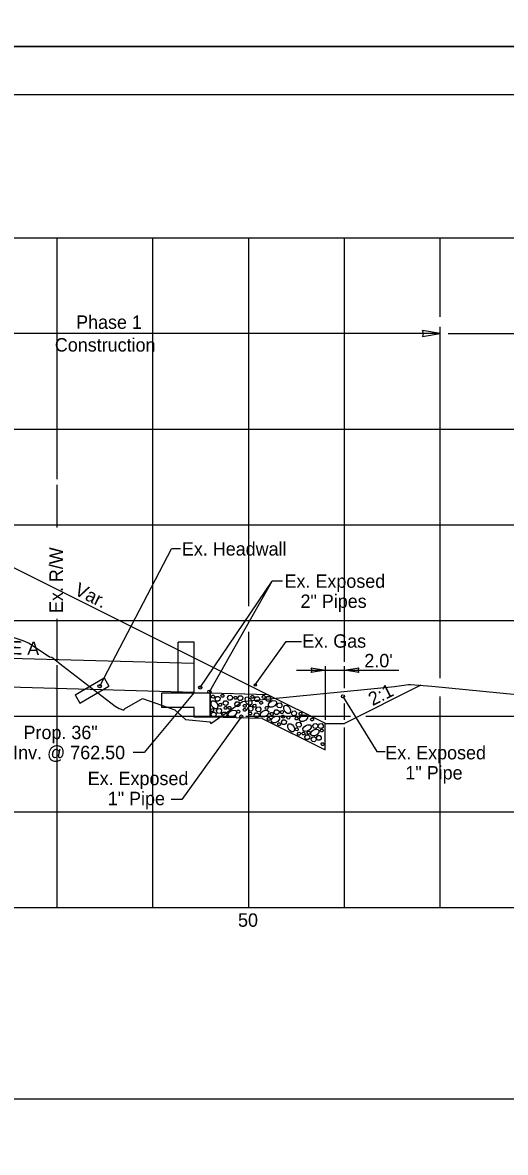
# Model space of a CAD drawing. Extents: x -1395 to 1843, y -1176 to 1887.
# Drawn here: x 387.8 to 488.6, y -671.2 to -435 of the extents above; entities that cross this region are included whole.
import ezdxf

# ---------------------------------------------------------------- set-up
doc = ezdxf.new("R2010")
doc.units = 0
for name, color, linetype in [('Default', 7, 'Continuous'), ('DR_P_Paved_Gutter', 7, 'Continuous'), ('DR_X_Storm_Sewer', 7, 'Continuous'), ('GE_X_Alignment', 7, 'Continuous'), ('HY_X_Water_Edge', 7, 'Continuous'), ('MT_P_Temp_Road', 7, 'Continuous'), ('PV_X_Shoulder', 7, 'Continuous'), ('RW_P_Esmt_TMP', 7, 'Continuous'), ('SH_Border', 7, 'Continuous'), ('SH_Cut_Line', 7, 'Continuous'), ('SH_Data', 7, 'Continuous'), ('SH_Major_Grid_Line', 7, 'Continuous'), ('SH_Named_Boundary', 7, 'Continuous'), ('SV_X_Shot_Marker', 7, 'Continuous'), ('SV_X_Terrain_Boundary', 7, 'Continuous'), ('SV_X_Toe_of_Slope', 7, 'Continuous'), ('SV_X_Top_of_Bank', 7, 'Continuous'), ('XS_P_Pavt_Surface', 7, 'Continuous')]:
    doc.layers.add(name, color=color, linetype=linetype)

msp = doc.modelspace()

# ---------------------------------------------------------------- linework, layer by layer
at = {"layer": 'Default'}
for p, q in [((475, -500), (471.29, -499.38)), ((471.29, -499.38), (471.29, -499.38)), ((471.3, -500.62), (475, -500)), ((471.3, -500.62), (471.3, -500.62))]:
    msp.add_line(p, q, dxfattribs=at)
msp.add_arc((470.36, -500.01), 1.12, 327.1412, 33.822, dxfattribs=at)
at = {"layer": 'DR_P_Paved_Gutter'}
for p, q in [((426.95, -575.17), (426.95, -580.17)), ((439.08, -575.51), (426.95, -575.17)), ((439.08, -575.51), (450.95, -581.44)), ((437.84, -580.47), (426.95, -580.17)), ((437.84, -580.47), (450.95, -587.03)), ((450.95, -587.03), (450.95, -581.44))]:
    msp.add_line(p, q, dxfattribs=at)
for points in [[(427.21, -575.85), (427.38, -575.62), (427.65, -575.6), (427.84, -575.79), (427.81, -576.06), (427.64, -576.2), (427.38, -576.18), (427.25, -576.06), (427.21, -575.85)], [(427.98, -576.27), (428.26, -575.87), (428.7, -575.84), (429.01, -576.16), (428.97, -576.62), (428.69, -576.85), (428.25, -576.81), (428.04, -576.61), (427.98, -576.27)], [(429.21, -575.69), (429.38, -575.45), (429.64, -575.44), (429.83, -575.63), (429.8, -575.9), (429.64, -576.04), (429.37, -576.02), (429.25, -575.9), (429.21, -575.69)], [(430.54, -576.05), (430.82, -575.65), (431.27, -575.62), (431.58, -575.95), (431.53, -576.4), (431.26, -576.63), (430.82, -576.6), (430.61, -576.39), (430.54, -576.05)], [(431.92, -576.09), (432.09, -575.85), (432.36, -575.84), (432.55, -576.03), (432.52, -576.3), (432.35, -576.44), (432.09, -576.42), (431.97, -576.3), (431.92, -576.09)], [(432.74, -576.14), (433.02, -575.74), (433.46, -575.71), (433.78, -576.04), (433.73, -576.49), (433.45, -576.72), (433.01, -576.69), (432.81, -576.48), (432.74, -576.14)], [(435.46, -576.43), (435.66, -576.96), (435.62, -577.44), (435.4, -577.67), (435.01, -577.66), (434.57, -577.31), (434.3, -576.78), (434.29, -576.27), (434.49, -575.99), (434.9, -575.96), (435.26, -576.19), (435.47, -576.45)], [(435.46, -575.89), (435.62, -575.65), (435.89, -575.64), (436.08, -575.83), (436.05, -576.1), (435.89, -576.24), (435.62, -576.22), (435.5, -576.1), (435.46, -575.89)], [(436.22, -576.35), (436.5, -575.95), (436.95, -575.93), (437.26, -576.25), (437.21, -576.7), (436.94, -576.93), (436.49, -576.9), (436.29, -576.7), (436.22, -576.35)], [(437.82, -575.92), (437.99, -575.68), (438.25, -575.67), (438.44, -575.86), (438.41, -576.13), (438.25, -576.27), (437.98, -576.25), (437.86, -576.13), (437.82, -575.92)], [(438.6, -576.27), (438.88, -575.87), (439.33, -575.84), (439.64, -576.17), (439.6, -576.62), (439.32, -576.85), (438.88, -576.82), (438.67, -576.61), (438.61, -576.27)], [(427.06, -578.66), (427.23, -578.42), (427.5, -578.4), (427.68, -578.6), (427.66, -578.87), (427.49, -579), (427.23, -578.99), (427.1, -578.86), (427.06, -578.66)], [(428.34, -577.22), (428.55, -577.74), (428.5, -578.23), (428.29, -578.46), (427.9, -578.45), (427.45, -578.1), (427.18, -577.56), (427.17, -577.06), (427.38, -576.77), (427.78, -576.75), (428.14, -576.98), (428.35, -577.24)], [(428.29, -578.82), (428.57, -578.43), (429.02, -578.4), (429.33, -578.72), (429.28, -579.17), (429.01, -579.4), (428.56, -579.37), (428.36, -579.17), (428.29, -578.82)], [(428.72, -577.54), (428.89, -577.3), (429.16, -577.29), (429.34, -577.48), (429.32, -577.75), (429.15, -577.89), (428.88, -577.87), (428.76, -577.75), (428.72, -577.54)], [(429.67, -577.16), (429.95, -576.76), (430.39, -576.74), (430.71, -577.06), (430.66, -577.51), (430.38, -577.74), (429.94, -577.71), (429.74, -577.51), (429.67, -577.16)], [(429.84, -578.21), (430.01, -577.97), (430.28, -577.95), (430.46, -578.15), (430.44, -578.42), (430.27, -578.55), (430, -578.54), (429.88, -578.41), (429.84, -578.21)], [(430.67, -578.18), (430.84, -577.94), (431.1, -577.93), (431.29, -578.12), (431.26, -578.39), (431.1, -578.53), (430.83, -578.51), (430.71, -578.39), (430.67, -578.18)], [(432.13, -577.41), (432.41, -577.01), (432.86, -576.99), (433.17, -577.31), (433.13, -577.76), (432.85, -577.99), (432.41, -577.96), (432.2, -577.76), (432.13, -577.41)], [(433.85, -578.6), (434.02, -578.36), (434.29, -578.35), (434.48, -578.54), (434.45, -578.81), (434.29, -578.95), (434.02, -578.93), (433.9, -578.81), (433.85, -578.6)], [(433.87, -577.78), (434.03, -577.55), (434.3, -577.53), (434.49, -577.72), (434.46, -577.99), (434.3, -578.13), (434.03, -578.11), (433.91, -577.99), (433.87, -577.78)], [(434.85, -578.32), (435.13, -577.92), (435.58, -577.89), (435.89, -578.22), (435.85, -578.67), (435.57, -578.9), (435.13, -578.87), (434.92, -578.67), (434.85, -578.32)], [(435.89, -577.75), (436.06, -577.51), (436.33, -577.5), (436.52, -577.69), (436.49, -577.96), (436.32, -578.1), (436.06, -578.08), (435.94, -577.96), (435.89, -577.75)], [(436.5, -578.49), (436.78, -578.09), (437.23, -578.06), (437.54, -578.38), (437.49, -578.84), (437.22, -579.07), (436.77, -579.03), (436.57, -578.83), (436.5, -578.49)], [(437.27, -577.14), (437.44, -576.9), (437.71, -576.88), (437.89, -577.08), (437.87, -577.35), (437.7, -577.49), (437.43, -577.47), (437.31, -577.34), (437.27, -577.14)], [(438.43, -578.21), (438.6, -577.97), (438.87, -577.96), (439.05, -578.15), (439.02, -578.42), (438.86, -578.56), (438.59, -578.54), (438.47, -578.42), (438.43, -578.21)], [(439.58, -576.91), (440.11, -576.71), (440.59, -576.75), (440.82, -576.96), (440.81, -577.36), (440.46, -577.8), (439.93, -578.07), (439.42, -578.08), (439.14, -577.87), (439.11, -577.47), (439.34, -577.11), (439.6, -576.9)], [(440.89, -577.64), (441.17, -577.25), (441.62, -577.22), (441.93, -577.54), (441.89, -577.99), (441.61, -578.22), (441.17, -578.19), (440.96, -577.99), (440.89, -577.64)], [(443.5, -578.18), (443.71, -578.71), (443.67, -579.19), (443.45, -579.42), (443.06, -579.41), (442.61, -579.06), (442.34, -578.53), (442.34, -578.02), (442.54, -577.74), (442.94, -577.71), (443.3, -577.94), (443.51, -578.2)], [(427.13, -579.53), (427.41, -579.13), (427.86, -579.11), (428.17, -579.43), (428.12, -579.88), (427.84, -580.11), (427.4, -580.08), (427.2, -579.88), (427.13, -579.53)], [(429.42, -579.55), (429.7, -579.15), (430.15, -579.12), (430.46, -579.45), (430.42, -579.9), (430.14, -580.13), (429.7, -580.1), (429.49, -579.89), (429.42, -579.55)], [(431.21, -578.94), (431.73, -578.73), (432.21, -578.78), (432.44, -578.99), (432.43, -579.38), (432.09, -579.83), (431.55, -580.1), (431.04, -580.11), (430.76, -579.9), (430.73, -579.5), (430.96, -579.14), (431.23, -578.93)], [(432.5, -578.97), (432.67, -578.73), (432.94, -578.72), (433.12, -578.91), (433.1, -579.18), (432.93, -579.32), (432.66, -579.3), (432.54, -579.18), (432.5, -578.97)], [(434.99, -579.38), (435.16, -579.14), (435.43, -579.12), (435.61, -579.31), (435.59, -579.59), (435.42, -579.72), (435.16, -579.7), (435.03, -579.58), (434.99, -579.38)], [(436.11, -579.69), (436.39, -579.29), (436.84, -579.26), (437.15, -579.58), (437.1, -580.04), (436.83, -580.27), (436.39, -580.23), (436.18, -580.03), (436.11, -579.69)], [(437.93, -578.95), (438.46, -578.74), (438.94, -578.78), (439.17, -579), (439.16, -579.39), (438.81, -579.83), (438.28, -580.1), (437.77, -580.11), (437.49, -579.91), (437.46, -579.51), (437.69, -579.15), (437.96, -578.94)], [(438.86, -580.52), (439.03, -580.28), (439.3, -580.27), (439.48, -580.46), (439.46, -580.73), (439.29, -580.87), (439.03, -580.85), (438.9, -580.73), (438.86, -580.52)], [(439.51, -579.47), (439.68, -579.23), (439.95, -579.22), (440.13, -579.41), (440.11, -579.68), (439.94, -579.82), (439.68, -579.8), (439.55, -579.68), (439.51, -579.47)], [(440.18, -580.18), (440.71, -579.97), (441.19, -580.02), (441.42, -580.23), (441.41, -580.62), (441.06, -581.07), (440.52, -581.34), (440.02, -581.34), (439.73, -581.14), (439.71, -580.74), (439.94, -580.38), (440.2, -580.17)], [(440.3, -579.05), (440.58, -578.65), (441.02, -578.63), (441.33, -578.95), (441.29, -579.4), (441.01, -579.63), (440.57, -579.6), (440.36, -579.4), (440.3, -579.05)], [(441.62, -579.07), (441.79, -578.83), (442.06, -578.81), (442.25, -579.01), (442.22, -579.28), (442.06, -579.42), (441.79, -579.4), (441.67, -579.28), (441.63, -579.07)], [(441.83, -581.14), (442.11, -580.74), (442.56, -580.72), (442.87, -581.04), (442.82, -581.49), (442.55, -581.72), (442.11, -581.69), (441.9, -581.49), (441.83, -581.14)], [(441.86, -580.03), (442.02, -579.79), (442.29, -579.78), (442.48, -579.97), (442.45, -580.24), (442.29, -580.38), (442.02, -580.36), (441.9, -580.24), (441.86, -580.03)], [(442.96, -580.23), (443.13, -579.99), (443.4, -579.98), (443.58, -580.17), (443.55, -580.44), (443.39, -580.58), (443.12, -580.56), (443, -580.44), (442.96, -580.23)], [(443.94, -579.32), (444.22, -578.92), (444.66, -578.89), (444.97, -579.21), (444.93, -579.67), (444.65, -579.9), (444.21, -579.86), (444, -579.66), (443.94, -579.32)], [(444.67, -580.39), (444.84, -580.15), (445.1, -580.14), (445.29, -580.33), (445.26, -580.6), (445.1, -580.74), (444.83, -580.72), (444.71, -580.6), (444.67, -580.39)], [(445.5, -579.43), (445.67, -579.19), (445.94, -579.17), (446.12, -579.36), (446.1, -579.64), (445.93, -579.77), (445.67, -579.75), (445.54, -579.63), (445.5, -579.43)], [(446.05, -579.92), (446.58, -579.72), (447.06, -579.76), (447.29, -579.97), (447.28, -580.37), (446.93, -580.81), (446.39, -581.08), (445.89, -581.09), (445.6, -580.88), (445.58, -580.48), (445.81, -580.12), (446.07, -579.91)], [(447.92, -580.62), (448.09, -580.39), (448.36, -580.37), (448.54, -580.56), (448.52, -580.83), (448.35, -580.97), (448.08, -580.95), (447.96, -580.83), (447.92, -580.62)], [(441.01, -581.62), (441.18, -581.38), (441.45, -581.36), (441.64, -581.55), (441.61, -581.83), (441.44, -581.96), (441.18, -581.94), (441.06, -581.82), (441.01, -581.62)], [(444.35, -582.03), (444.56, -582.55), (444.52, -583.03), (444.3, -583.26), (443.91, -583.25), (443.47, -582.91), (443.2, -582.37), (443.19, -581.86), (443.39, -581.58), (443.79, -581.55), (444.15, -581.78), (444.36, -582.05)], [(444.7, -582.67), (444.87, -582.43), (445.14, -582.42), (445.33, -582.61), (445.3, -582.88), (445.13, -583.02), (444.87, -583), (444.74, -582.88), (444.7, -582.67)], [(444.93, -581.68), (445.21, -581.28), (445.65, -581.26), (445.96, -581.58), (445.92, -582.03), (445.64, -582.26), (445.2, -582.23), (444.99, -582.03), (444.93, -581.68)], [(446.11, -583.55), (446.28, -583.31), (446.54, -583.29), (446.73, -583.49), (446.7, -583.76), (446.54, -583.9), (446.27, -583.88), (446.15, -583.76), (446.11, -583.55)], [(446.81, -581.99), (447.33, -581.78), (447.81, -581.82), (448.04, -582.04), (448.04, -582.43), (447.69, -582.87), (447.15, -583.14), (446.65, -583.15), (446.36, -582.95), (446.33, -582.54), (446.57, -582.18), (446.83, -581.97)], [(447.19, -583.39), (447.35, -583.15), (447.62, -583.13), (447.81, -583.33), (447.78, -583.6), (447.62, -583.74), (447.35, -583.72), (447.23, -583.6), (447.19, -583.39)], [(448.43, -582.92), (448.96, -582.71), (449.44, -582.76), (449.67, -582.97), (449.66, -583.36), (449.31, -583.81), (448.78, -584.08), (448.27, -584.08), (447.99, -583.88), (447.96, -583.48), (448.19, -583.12), (448.46, -582.91)], [(448.37, -581.95), (448.65, -581.55), (449.1, -581.52), (449.41, -581.85), (449.36, -582.3), (449.09, -582.53), (448.65, -582.5), (448.44, -582.3), (448.37, -581.95)], [(449.52, -581.97), (449.8, -581.57), (450.25, -581.54), (450.56, -581.86), (450.52, -582.32), (450.24, -582.55), (449.8, -582.51), (449.59, -582.31), (449.52, -581.97)], [(449.93, -582.93), (450.1, -582.69), (450.37, -582.67), (450.55, -582.87), (450.53, -583.14), (450.36, -583.28), (450.1, -583.26), (449.97, -583.14), (449.93, -582.93)], [(445.17, -583.6), (445.34, -583.36), (445.61, -583.34), (445.8, -583.53), (445.77, -583.81), (445.6, -583.94), (445.34, -583.92), (445.21, -583.8), (445.17, -583.6)], [(446.7, -584.3), (446.98, -583.91), (447.43, -583.88), (447.74, -584.2), (447.69, -584.65), (447.42, -584.88), (446.97, -584.85), (446.77, -584.65), (446.7, -584.3)], [(448.03, -584.73), (448.31, -584.34), (448.76, -584.31), (449.07, -584.63), (449.03, -585.08), (448.75, -585.31), (448.31, -585.28), (448.1, -585.08), (448.04, -584.73)], [(449.12, -584.44), (449.4, -584.04), (449.85, -584.02), (450.16, -584.34), (450.11, -584.79), (449.84, -585.02), (449.4, -584.99), (449.19, -584.79), (449.12, -584.44)], [(450.13, -585.78), (450.3, -585.54), (450.57, -585.53), (450.75, -585.72), (450.72, -585.99), (450.56, -586.13), (450.29, -586.11), (450.17, -585.99), (450.13, -585.78)]]:
    msp.add_lwpolyline(points, dxfattribs=at)
at = {"layer": 'DR_X_Storm_Sewer'}
for p, q in [((373, -542.46), (439.08, -575.51)), ((470.93, -573.52), (455.02, -581.48)), ((451.02, -581.48), (450.95, -581.44)), ((451.02, -581.48), (455.02, -581.48))]:
    msp.add_line(p, q, dxfattribs=at)
at = {"layer": 'GE_X_Alignment'}
for p, q in [((115, -480), (555, -480)), ((475, -572.01), (475, -498.6)), ((403.88, -573.72), (418.89, -544.97)), ((420.75, -544.97), (418.89, -544.97)), ((424.88, -573.99), (439.88, -551.78)), ((426.8, -574.88), (439.88, -551.78)), ((442.05, -551.78), (439.88, -551.78)), ((436.38, -573.45), (442.83, -564.39)), ((442.83, -564.39), (446.02, -564.39)), ((444.95, -570.35), (451.02, -570.35)), ((451.02, -570.35), (448.05, -570.84)), ((448.05, -570.84), (448.06, -570.84)), ((448.06, -569.85), (448.06, -569.85)), ((448.06, -569.85), (451.02, -570.35)), ((451.02, -580.75), (451.02, -569.56)), ((451.02, -570.35), (455.02, -570.35)), ((455.02, -574.15), (455.02, -569.56)), ((455.02, -570.35), (457.99, -569.85)), ((457.98, -570.84), (455.02, -570.35)), ((455.02, -570.35), (466.33, -570.35)), ((457.98, -570.84), (457.98, -570.84)), ((457.99, -569.85), (457.99, -569.85)), ((423.6, -575), (413.17, -587.57)), ((454.68, -575.84), (461.77, -587.37)), ((455.02, -580.75), (455.02, -577.31)), ((433.46, -580.06), (421.04, -597.38)), ((413.17, -587.57), (410.9, -587.57)), ((461.77, -587.37), (463.49, -587.37)), ((421.04, -597.38), (418.78, -597.38))]:
    msp.add_line(p, q, dxfattribs=at)
for centre, start, end in [((447.31, -570.34), 326.178, 32.8588), ((458.74, -570.36), 146.178, 212.8588)]:
    msp.add_arc(centre, 0.9, start, end, dxfattribs=at)
at = {"layer": 'HY_X_Water_Edge'}
msp.add_lwpolyline([(381.03, -561.95), (387.85, -564.19), (389.13, -564.74), (393.39, -567.57), (393.88, -567.67), (396.27, -569.5), (407.15, -577.9), (407.92, -578.41), (408.94, -578.72), (409.08, -578.42), (412.85, -576.29), (419.55, -578.65), (421.81, -580.69), (426.89, -581.16), (427.07, -581.48), (433.7, -576.94), (465.43, -573.77), (468.33, -573.37), (468.79, -573.33), (473.24, -573.73), (501.62, -576.48)], dxfattribs=at)
at = {"layer": 'MT_P_Temp_Road'}
for p, q in [((423.6, -569), (335, -566.53)), ((423.6, -575), (423.6, -569)), ((423.6, -575), (335, -572.53))]:
    msp.add_line(p, q, dxfattribs=at)
at = {"layer": 'PV_X_Shoulder'}
msp.add_circle((436.38, -573.45), 0.25, dxfattribs=at)
at = {"layer": 'RW_P_Esmt_TMP'}
for p, q in [((395, -530.43), (395, -480)), ((415, -620), (415, -480)), ((435, -556.98), (435, -480)), ((455, -568.59), (455, -480)), ((475, -496.49), (475, -480)), ((476.61, -500), (555, -500)), ((336.74, -520), (555, -520)), ((115, -540), (555, -540)), ((115, -560), (555, -560)), ((435, -620), (435, -562.34)), ((395, -620), (395, -569.35)), ((475, -620), (475, -575.89)), ((115, -580), (432.4, -580)), ((434.41, -580), (456.26, -580)), ((459.44, -580), (555, -580)), ((455, -620), (455, -582.33)), ((115, -600), (555, -600)), ((115, -620), (555, -620))]:
    msp.add_line(p, q, dxfattribs=at)
at = {"layer": 'SH_Border'}
for points in [[(0, -440), (680, -440), (680, 0), (0, 0)], [(0, -880), (680, -880), (680, -440), (0, -440)]]:
    msp.add_lwpolyline(points, close=True, dxfattribs=at)
at = {"layer": 'SH_Cut_Line'}
msp.add_lwpolyline([(30, -450), (670, -450), (670, -870), (30, -870)], close=True, dxfattribs=at)
at = {"layer": 'SH_Major_Grid_Line'}
msp.add_line((475, -500), (335, -500), dxfattribs=at)
at = {"layer": 'SV_X_Shot_Marker'}
for centre in [(424.88, -573.99), (426.8, -574.88), (454.68, -575.84), (433.46, -580.06)]:
    msp.add_circle(centre, 0.333, dxfattribs=at)
at = {"layer": 'SV_X_Terrain_Boundary'}
for p, q in [((398.73, -575.49), (404.8, -571.99)), ((399.73, -577.23), (405.8, -573.73)), ((404.8, -571.99), (405.8, -573.73)), ((404.8, -571.99), (405.8, -573.73)), ((398.73, -575.49), (399.73, -577.23))]:
    msp.add_line(p, q, dxfattribs=at)
msp.add_circle((403.88, -573.72), 0.35, dxfattribs=at)
at = {"layer": 'SV_X_Toe_of_Slope'}
for p, q in [((420.25, -568.92), (420.25, -564.5)), ((423.6, -564.5), (420.25, -564.5)), ((423.6, -569), (423.6, -564.5)), ((420.25, -575.17), (420.25, -568.92)), ((416.89, -578.17), (416.89, -575.17)), ((426.95, -575.17), (416.89, -575.17)), ((426.95, -580.17), (426.95, -575.17)), ((423.6, -578.17), (416.89, -578.17)), ((423.6, -580.17), (423.6, -578.17)), ((426.95, -580.17), (423.6, -580.17))]:
    msp.add_line(p, q, dxfattribs=at)
at = {"layer": 'SV_X_Top_of_Bank'}
for p, q in [((395, -540.54), (395, -531.62)), ((395, -568.53), (395, -559.6))]:
    msp.add_line(p, q, dxfattribs=at)
at = {"layer": 'XS_P_Pavt_Surface'}
msp.add_line((30, -660), (640, -660), dxfattribs=at)

# ---------------------------------------------------------------- texts
at = {"layer": 'SH_Data'}
for s, p in [('Ex. Headwall', (421.05, -546.41)), ('Ex. Exposed', (442.48, -553.15)), ('2" Pipes', (445.81, -557.35)), ('Ex. Gas', (446.2, -565.67)), ("2.0'", (459.14, -569.77)), ('Prop. 36"', (387.98, -584.78)), (' Inv. @ 762.50', (384.78, -588.98)), ('Ex. Exposed', (463.52, -589.01)), ('1" Pipe', (467.71, -593.21)), ('Ex. Exposed', (401.38, -594.39)), ('1" Pipe', (405.57, -598.59)), ('50', (432.77, -624))]:
    msp.add_text(s, height=2.8, dxfattribs=at).set_placement(p)
for s, rotation, p in [('Var.', 333.4349, (398.4, -554.46)), ('PROP. CONDUIT, BORED OR JACKED, 36" CONDUIT, TYPE A', 358.3999, (282.61, -564.18)), ('2:1', 26.5651, (460.86, -577.89))]:
    msp.add_text(s, height=2.8, rotation=rotation, dxfattribs=at).set_placement(p)
at = {"layer": 'SH_Named_Boundary'}
for s, p in [('Phase 1', (398.96, -499.01)), ('Construction', (394.52, -503.76))]:
    msp.add_text(s, height=2.8, rotation=359.9439, dxfattribs=at).set_placement(p)
at = {"layer": 'SV_X_Top_of_Bank'}
msp.add_text('Ex. R/W', height=2.8, rotation=90, dxfattribs=at).set_placement((396.19, -558.41))

doc.saveas('drawing.dxf')
